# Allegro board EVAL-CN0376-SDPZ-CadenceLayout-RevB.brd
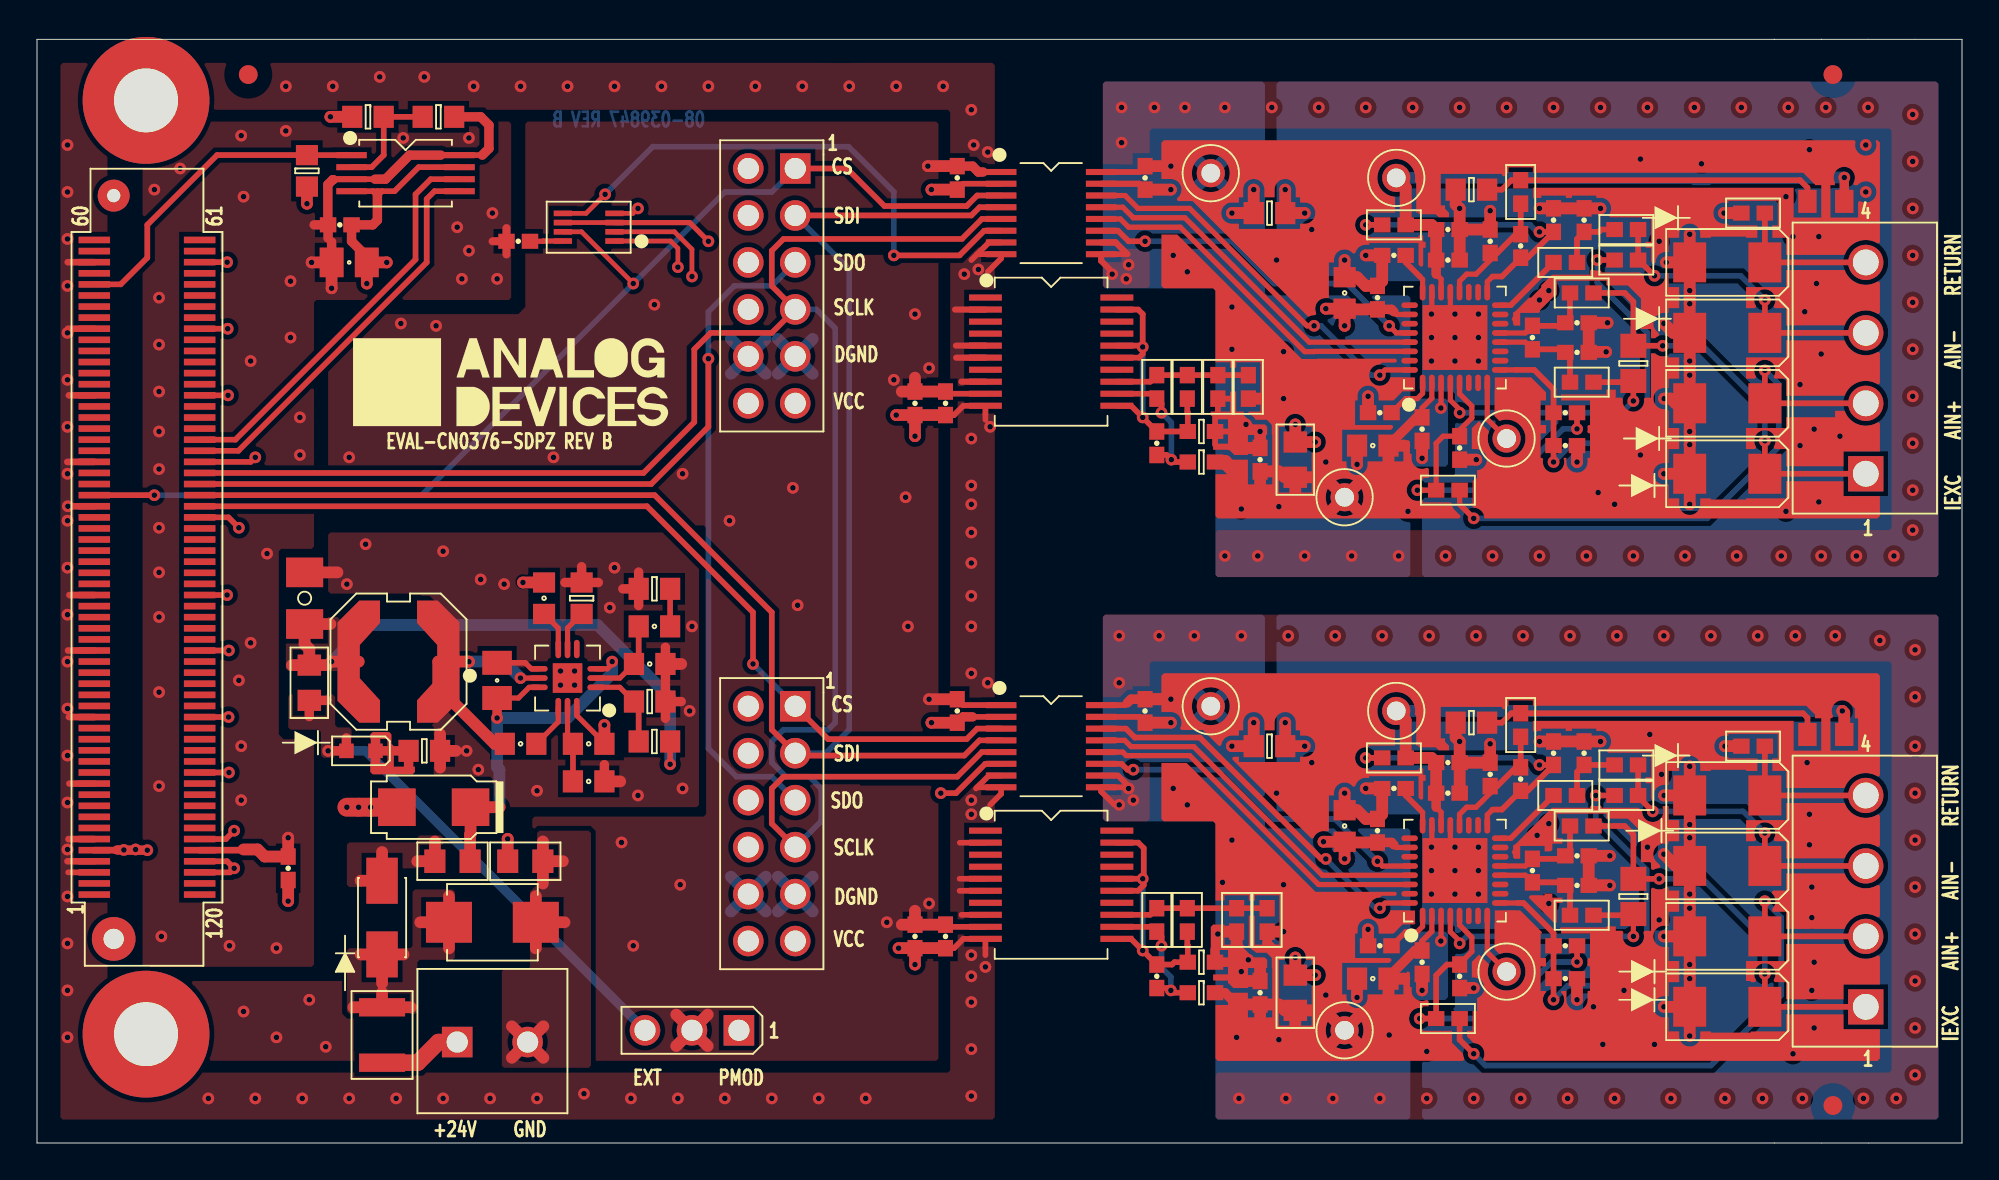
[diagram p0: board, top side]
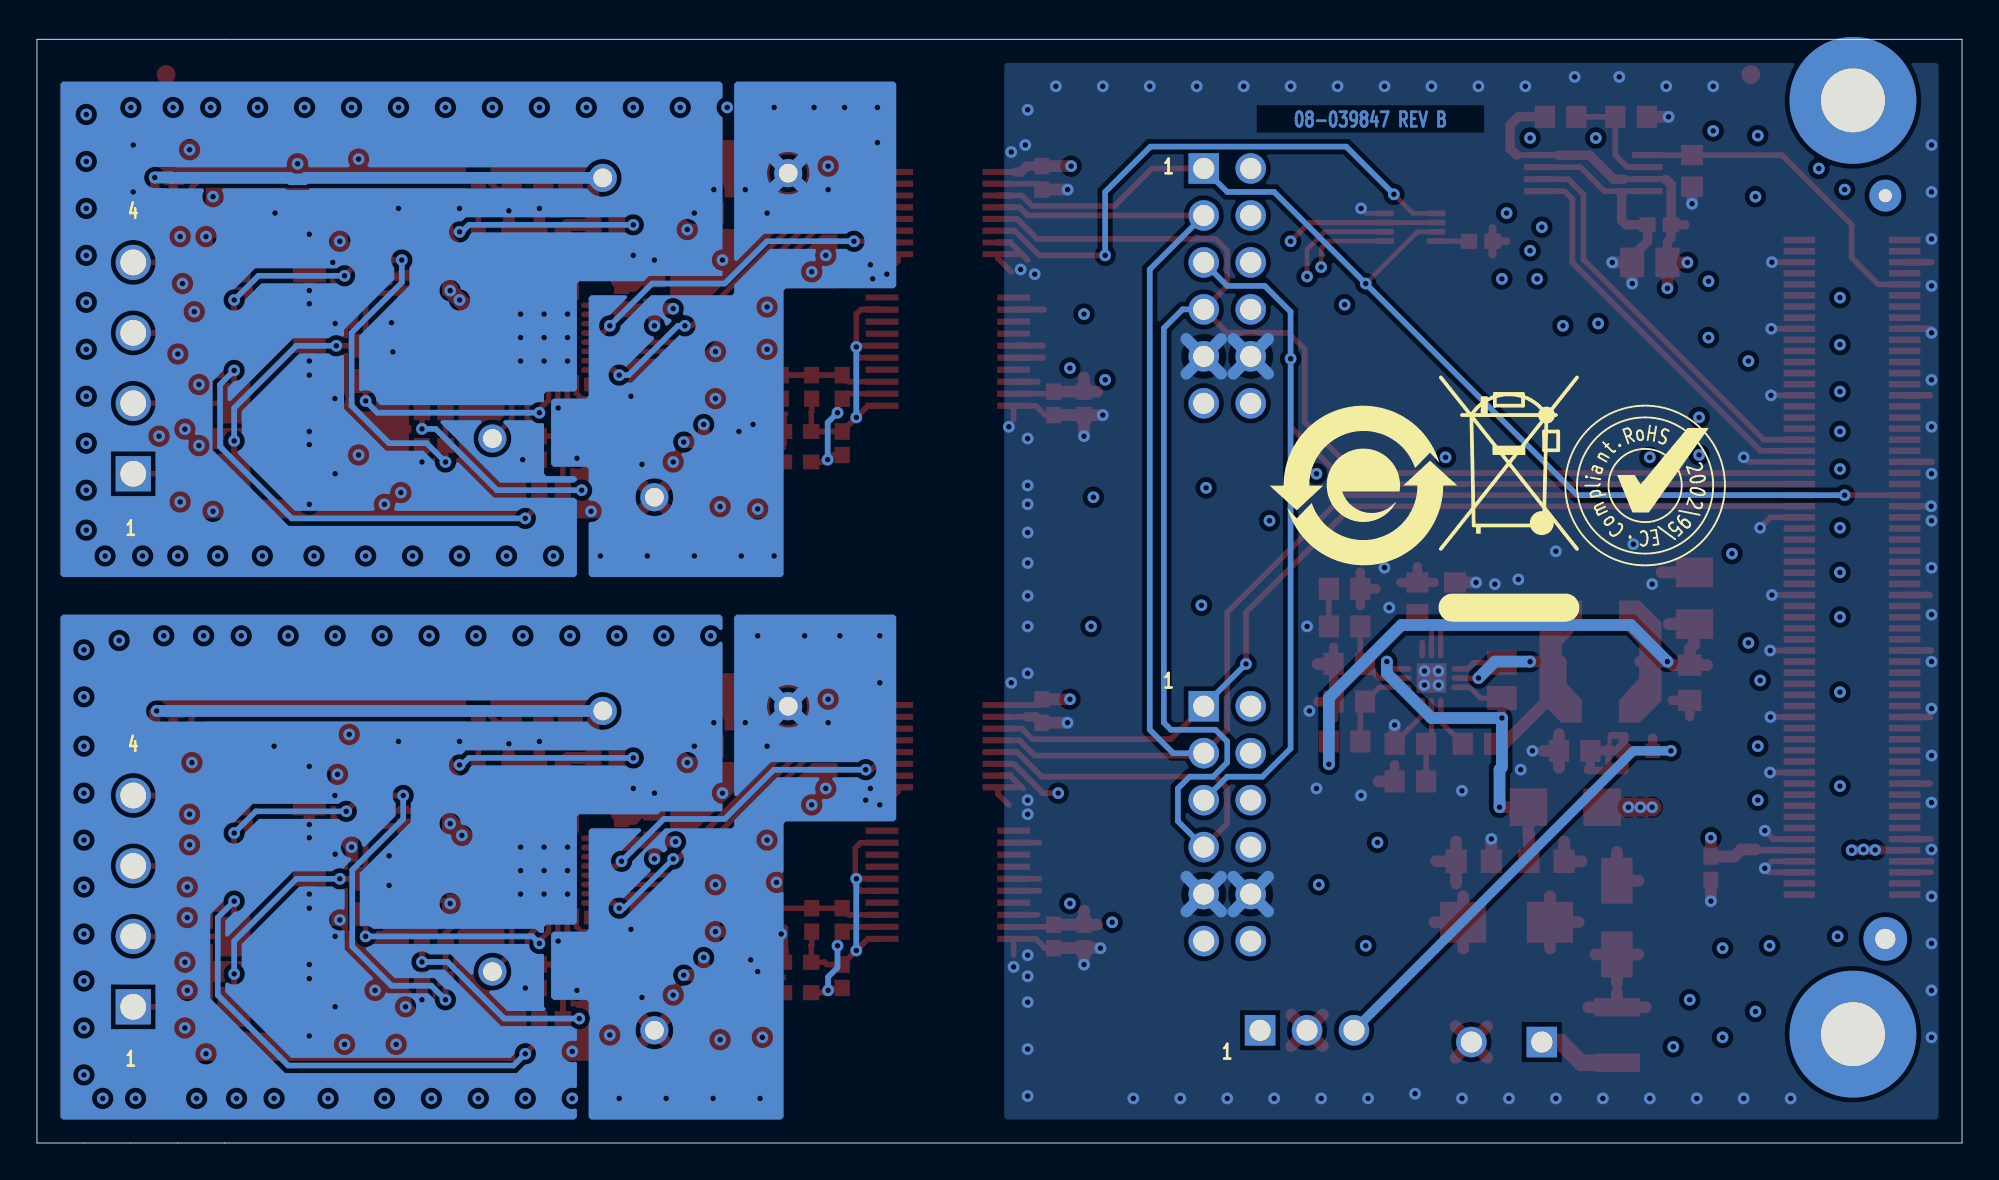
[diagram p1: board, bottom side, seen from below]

Outline 104.14 x 59.69 mm; copper layers: TOP, L2_GND, L3_PWR, BOTTOM. Coordinates in mm from the lower left corner of the outline.
Outline path: 0,59.69 0,0 104.14,0 104.14,59.69 0,59.69

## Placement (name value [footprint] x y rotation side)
AIN2A  5002  [CNKEY5001TP]  79.5 9.27 0 top
AIN2B  5002  [CNKEY5001TP]  79.5 38.1 0 top
C1  1000pF  [C0402]  76.96 9.02 270 top
C2  1000pF  [C0402]  82.68 8.89 180 top
C3  10000pF  [C0402]  82.68 10.67 180 top
C4  1000pF  [C0402]  83.31 13.93 0 top
C5  1000pF  [C0402]  83.31 15.53 180 top
C6  10000pF  [C0402]  80.9 14.73 90 top
C7  10000pF  [C0402]  80.26 19.68 270 top
C8  1000pF  [C0402]  78.61 19.94 90 top
C9  1UF  [C0603]  72.26 8.89 0 top
C10  0.1uF  [C0402]  74.93 9.78 90 top
C11  0.1uF  [C0402]  72.52 16.89 270 top
C12  1UF  [C0603]  70.74 17.14 270 top
C13  10uF  [C0402]  66.17 8.13 90 top
C14  0.1uF  [C0402]  72.64 10.67 0 top
C15  0.1uF  [C0402]  73.41 19.18 0 top
C16  0.1UF  [C0402]  60.58 9.02 90 top
C17  0.1UF  [C0402]  59.94 23.37 270 top
C18  0.1UF  [C0402]  49.15 11.17 270 top
C19  0.1UF  [C0402]  49.78 23.37 270 top
C20  10uF  [C0402]  47.5 11.17 270 top
C21  1000pF  [C0402]  76.96 37.59 270 top
C22  1000pF  [C0402]  82.68 37.72 180 top
C23  10000pF  [C0402]  82.68 39.5 180 top
C24  1000pF  [C0402]  83.31 42.76 0 top
C25  1000pF  [C0402]  83.31 44.36 180 top
C26  10000pF  [C0402]  80.9 43.56 90 top
C27  10000pF  [C0402]  80.26 48.51 270 top
C28  1000pF  [C0402]  78.61 48.77 90 top
C29  10uF  [C0402]  66.17 36.96 90 top
C30  0.1UF  [C0402]  60.58 37.85 90 top
C31  0.1UF  [C0402]  49.15 40 270 top
C32  10uF  [C0402]  47.5 40 270 top
C33  1UF  [C0603]  72.26 37.72 0 top
C34  0.1uF  [C0402]  74.93 38.61 90 top
C35  0.1uF  [C0402]  72.52 45.72 270 top
C36  1UF  [C0603]  70.74 45.97 270 top
C37  0.1uF  [C0402]  72.64 39.5 0 top
C38  0.1uF  [C0402]  73.41 48.01 0 top
C39  0.1UF  [C0402]  59.94 52.2 270 top
C40  0.1UF  [C0402]  49.78 52.2 270 top
C41  2.2uF  [C0805H60]  24.89 25.02 90 top
C42  1000pF  [C0603]  33.4 27.94 0 top
C43  8.2PF  [C0603]  33.15 25.91 0 top
C44  0.01uF  [C0603]  27.43 29.46 90 top
C45  0.01uF  [C0603]  26.16 21.59 180 top
C46  1uF  [C0603]  29.84 21.59 180 top
C47  1uF  [C0603]  29.84 19.56 0 top
C48  10uF  [C1206H71]  14.48 29.46 90 top
C49  0.1uF  [C0402]  13.59 14.86 90 top
C50  10uF  [C0805]  16.89 47.62 180 top
C51  0.1UF  [C0402]  16.38 49.66 180 top
C52  0.1uF  [C0402]  76.33 18.92 180 top
C53  0.1uF  [C0402]  76.33 47.75 180 top
C56  0.1uF  [C0402]  83.69 21.08 270 top
C57  1uF  [C0402]  76.33 20.57 0 top
C60  0.1uF  [C0402]  83.69 49.91 270 top
C61  1uF  [C0402]  76.33 49.4 0 top
C62  1000pF  [C0402]  82.04 21.08 90 top
C63  1000pF  [C0402]  82.04 49.91 90 top
C64  0.1UF  [C0402]  26.04 48.77 180 top
D1  SMBJ36CA  [DO214AA-5]  24.64 11.94 180 top
D2  SBR1A40SA-13  [SMA-2]  18.67 12.19 270 top
D3  SMAJ36A  [DO214AC]  91.44 7.37 180 top
D4  SMAJ36A  [DO214AC]  91.44 11.18 180 top
D5  SMAJ36A  [DO214AC]  91.44 14.99 180 top
D6  SMAJ36A  [DO214AC]  91.44 18.8 180 top
D7  SMAJ36A  [DO214AC]  91.44 36.19 180 top
D8  SMAJ36A  [DO214AC]  91.44 40 180 top
D9  SMAJ36A  [DO214AC]  91.44 43.81 180 top
D10  SMAJ36A  [DO214AC]  91.44 47.62 180 top
D11  MBRA340T3G  [SMA]  21.46 18.16 180 top
DS1  LNJ312G83RA (green)  [LED0603-2]  17.53 21.21 180 top
DVDD1  5002  [CNKEY5001TP]  70.74 6.1 0 top
DVDD2  5002  [CNKEY5001TP]  70.74 34.92 0 top
E1  0  [R0603]  66.67 21.46 180 top
E2  0  [R0603]  66.67 50.29 180 top
E3  330OHM  [L0805]  68.07 8.13 270 top
E4  330OHM  [L0805]  68.07 36.96 270 top
E5  330OHM  [L0805]  22.48 15.24 0 top
E6  330OHM  [L0805]  26.42 15.24 180 top
E7  1K OHM  [L0805]  14.73 24.89 270 top
E8  1KOHM AT 100MHZ  [L0603]  62.99 8.13 180 top
E9  1KOHM AT 100MHZ  [L0603]  62.99 9.78 180 top
E10  1KOHM AT 100MHZ  [L0603]  62.99 36.83 180 top
E11  1KOHM AT 100MHZ  [L0603]  62.99 38.48 180 top
F1  0.20A  [F1210]  18.67 5.84 90 top
GND1  5001  [CNKEY5001TP]  63.5 23.62 0 top
GND2  5001  [CNKEY5001TP]  63.5 52.45 0 top
L1  22uH  [LSMSQ236H138]  19.56 26.03 180 top
NOREF  -  []  25.65 41.15 0 top
NOREF#2  -  []  96.8 0 90 top
NOREF#3  -  [unnamed#2]  97.16 57.78 0 top
NOREF#4  -  [unnamed#2]  97.16 2.03 0 top
NOREF#5  -  []  0 0 0 top
NOREF#6  -  []  11.43 57.78 0 top
NOREF#7  -  [unnamed#2]  11.43 57.78 0 top
NOREF#8  -  []  -175.26 -209.3 0 top
NOREF#9  -  []  0 59.69 0 top
NOREF#10  -  []  182.25 258.06 0 top
NOREF#11  -  []  46.35 92.07 0 top
NOREF#12  -  []  101.6 59.69 0 top
NOREF#13  -  []  0 1.85 0 top
NOREF#14  -  []  97.79 -22.86 90 top
NOREF#15  -  []  0 -22.86 0 top
NOREF#16  -  []  -184.15 -219.71 0 top
NOREF#17  -  []  -182.88 -218.44 0 top
NOREF#18  -  []  0 59.69 0 top
NOREF#19  -  []  97.79 59.69 180 top
NOREF#20  -  []  101.6 59.69 0 top
NOREF#21  -  []  11.43 57.78 0 top
NOREF#22  -  []  -37.08 259.21 0 top
NOREF#23  -  []  0 59.69 270 top
NOREF#24  -  []  0 0 0 top
NOREF#25  -  []  186.82 5.84 180 bottom
NOREF#26  -  []  15.24 45.08 180 bottom
NOREF#27  -  []  32.38 35.56 180 bottom
NOREF#28  -  []  17.14 35.56 180 bottom
P1  1727036  [CNPHOENIX1727036]  98.93 7.37 90 top
P2  1727036  [CNPHOENIX1727036]  98.93 36.19 90 top
P3  1727010  [CNTH1X2H335_A]  22.73 5.46 0 top
P4  HTSW-106-08-G-D  [CNHDR2X6H330LD35_A]  41.02 23.62 270 top
P5  HTSW-106-08-G-D  [CNHDR2X6H330LD35_A]  41.02 52.7 270 top
PWR_SEL  SAMTECTSW10608GS3PIN  [CNBERG1X3H205LD36]  37.97 6.1 180 top
R1  3K  [R0402]  92.84 21.46 180 top
R3  3K  [R0402]  76.33 6.73 180 top
R4  3K  [R0402]  85.98 18.8 180 top
R5  3K  [R0402]  85.98 20.45 180 top
R6  3.92K  [R0805]  86.36 13.33 90 top
R8  3K  [R0402]  83.57 12.32 180 top
R9  3K  [R0402]  83.57 17.14 180 top
R10  5.62K  [R0603]  77.6 22.73 180 top
R11  3K  [R0402]  80.26 22.61 270 top
R12  10K  [R0402]  64.9 12.06 270 top
R13  16.9K  [R0402]  66.55 12.06 270 top
R14  10K  [R0402]  62.23 12.06 270 top
R15  16.9K  [R0402]  60.58 12.06 270 top
R16  3K  [R0402]  92.84 50.29 180 top
R18  3K  [R0402]  85.98 47.75 180 top
R19  3K  [R0402]  85.98 49.4 180 top
R20  3K  [R0402]  76.33 35.31 180 top
R21  3.92K  [R0805]  86.36 42.16 90 top
R23  3K  [R0402]  83.57 41.15 180 top
R24  3K  [R0402]  83.57 45.97 180 top
R25  5.62K  [R0603]  77.6 51.56 180 top
R26  3K  [R0402]  80.26 51.43 270 top
R27  10K  [R0402]  63.88 40.89 270 top
R28  16.9K  [R0402]  65.53 40.89 270 top
R29  10K  [R0402]  62.23 40.89 270 top
R30  16.9K  [R0402]  60.58 40.89 270 top
R31  294K  [R0603]  29.46 29.46 90 top
R32  32.4K  [R0603]  33.4 29.97 180 top
R33  13.7K  [R0603]  33.15 23.88 180 top
R34  61.9K  [R0603]  33.4 21.72 0 top
R35  130  [R0603]  20.95 21.21 0 top
R36  100K  [R0603]  14.61 52.58 270 top
R37  100K  [R0603]  21.72 55.5 180 top
R38  100K  [R0603]  17.91 55.5 180 top
R39  3K  [R0402]  73.41 20.83 180 top
R40  3K  [R0402]  73.41 49.66 180 top
R43  10  [R0402]  82.68 18.8 180 top
R46  10  [R0402]  82.68 47.62 180 top
REF1  5002  [CNKEY5001TP]  73.53 23.37 0 top
REF2  5002  [CNKEY5001TP]  73.53 52.2 0 top
RT1  10K  [R0805H51]  96.77 22.1 180 top
RT2  10K  [R0805H51]  96.77 50.93 180 top
SDP  FX8-120S-SV(21)  [CNHRSFX8-120S-SV_A]  5.95 31.14 90 top
U1  AD7124-4BCPZ  [QFN32_5X5_PAD3_5X3_5]  76.71 14.73 0 top
U2  ADUM5010ARSZ  [SSOP20-4]  54.86 13.97 270 top
U3  ADuM1441ARQZ  [QSOP16]  54.86 21.46 270 top
U4  ADUM5010ARSZ  [SSOP20-4]  54.86 42.8 270 top
U5  AD7124-4BCPZ  [QFN32_5X5_PAD3_5X3_5]  76.71 43.56 0 top
U6  ADuM1441ARQZ  [QSOP16]  54.86 50.29 270 top
U7  ADP2441ACPZ  [QFN12_3X3_PAD1_6X1_6]  28.7 25.15 90 top
U8  24LC32A-I/ST  [TSSOP8]  19.94 52.45 270 top
U9  SN74LVC2G125DCUT  [US8-2]  29.84 49.53 90 top

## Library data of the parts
AIN2A AIN2B DVDD1 DVDD2 REF1 REF2 = CNTP1P: User Part Number: UPN; alternate symbols: (CNBANANA_ALT); part number: CNTP1P_TH-5002,E006153,CNKEY5001TP
C1 C2 C4 C5 C8 C21 C22 C24 C25 C28 C62 C63 = CAP: Tolerance: 10; User Part Number: UPN; part number: CAP_SM-1000PF,50V,10,E020689,C0402; tolerance: 10
C3 C6 C23 C26 = CAP: Tolerance: 2; User Part Number: UPN; part number: CAP_SM-10000PF,16V,2,E015834,C0402; tolerance: 2
C7 C27 = CAP: Tolerance: 10; User Part Number: UPN; part number: CAP_SM-10000PF,50V,10,E021852,C0402; tolerance: 10
C9 C12 C33 C36 = CAP: Tolerance: 10; User Part Number: UPN; part number: CAP_SM-1UF,25V,10,E006992,C0603; tolerance: 10
C10 C11 C14 C15 C34 C35 C37 C38 C49 C52 C53 C56 C60 = CAP: Tolerance: -0.25; User Part Number: UPN; part number: CAP_SM-0.1UF,25V,-0.25,E011876,C0402; tolerance: -0.25
C13 C20 C29 C32 = CAP: Tolerance: 20; User Part Number: UPN; part number: CAP_SM-10UF,10V,20,E020928,C0402; tolerance: 20
C16-C19 C30 C31 C39 C40 C51 C64 = CAP: Tolerance: 10; User Part Number: UPN; part number: CAP_SM-0.1UF,16V,10,E007200,C0402; tolerance: 10
C41 = CAP: Tolerance: 20; User Part Number: UPN; part number: CAP_SM-2.2UF,50V,20,E016010,C0805H60; tolerance: 20
C42 = CAP: Tolerance: 10; User Part Number: UPN; part number: CAP_SM-1000PF,50V,10,E018586,C0603; tolerance: 10
C43 = CAP: Tolerance: 0.25PF; User Part Number: UPN; part number: CAP_SM-8.2PF,50V,0.25PF,E000346,C0603; tolerance: 0.25PF
C44 C45 = CAP: Tolerance: 5; User Part Number: UPN; part number: CAP_SM-0.01UF,25V,5,E012400,C0603; tolerance: 5
C46 C47 = CAP: Tolerance: 10; User Part Number: UPN; part number: CAP_SM-1UF,10V,10,E011783,C0603; tolerance: 10
C48 = CAP: Tolerance: 10; User Part Number: UPN; part number: CAP_SM-10UF,50V,10,E013961,C1206H71; tolerance: 10
C50 = CAP: Tolerance: 10; User Part Number: UPN; part number: CAP_SM-10UF,25V,10,E019080,C0805; tolerance: 10
C57 C61 = CAP: Tolerance: 20; User Part Number: UPN; part number: CAP_SM-1UF,16V,20,E020695,C0402; tolerance: 20
D1 = DIO_V3: Tolerance: N/A; User Part Number: UPN; part number: DIO_V3_SM-SMBJ36CA,36V,N/A,E019417,DO214AA-5; tolerance: N/A
D2 = DIO: User Part Number: UPN; Tolerance: N/A; alternate symbols: (DO15_ALT); part number: DIO_SM-SBR1A40SA-13,40V,N/A,E015547,SMA-2; tolerance: N/A
D3-D10 = DIO: User Part Number: UPN; Tolerance: 5; alternate symbols: (DO15_ALT); part number: DIO_SM-SMAJ36A,36V,5,E007236,DO214AC; tolerance: 5
D11 = DIOSCHOTTKY: User Part Number: UPN; Tolerance: N/A; alternate symbols: (SOD882L_ALT); part number: DIOSCHOTTKY_SM-MBRA340T3G,40V,N/A,E012714,SMA; tolerance: N/A
DS1 = DIOLED: Tolerance: N/A; User Part Number: UPN; part number: DIOLED_SM-LNJ312G83RA (GREEN),2.03V,N/A,E014696,LED0603-2; tolerance: N/A
E1 E2 = RES: Tolerance: 5; User Part Number: UPN; part number: RES_SM-0,E006826,1/10W,5,R0603; tolerance: 5
E3-E6 = FERRITE: Tolerance: 25; User Part Number: UPN; alternate symbols: (L1210H59_ALT); part number: FERRITE_SM-330OHM,25,E018120,L0805; tolerance: 25
E7 = FERRITE: Tolerance: N/A; User Part Number: UPN; alternate symbols: (L1210H59_ALT); part number: FERRITE_SM-1K OHM,N/A,E011583,L0805; tolerance: N/A
E8-E11 = FERRITE: Tolerance: 25; User Part Number: UPN; alternate symbols: (L1210H59_ALT); part number: FERRITE_SM-1KOHM AT 100MHZ ,25,E023240,L0603; tolerance: 25
F1 = FSFUSE: User Part Number: UPN; part number: FSFUSE_SM-0.20A,30V,E016947,F1210
GND1 GND2 = CNTP1P: User Part Number: UPN; alternate symbols: (CNBANANA_ALT); part number: CNTP1P_TH-5001,E005347,CNKEY5001TP
L1 = IND: User Part Number: UPN; Tolerance: 20; alternate symbols: (L0402-2,L0603_ALT,L1008L_ALT); part number: IND_SM-22UH,20,E022264,LSMSQ236H138; tolerance: 20
P1 P2 = CN4P: User Part Number: UPN; part number: CN4P_TH-1727036,E022262,CNPHOENIX1727036
P3 = CN2P: User Part Number: UPN; part number: CN2P_TH-1727010,E019958,CNTH1X2H335_A
P4 P5 = CN12P_V3: User Part Number: UPN; part number: CN12P_V3_TH-HTSW-106-08-G-D,E021590,CNHDR2X6H330LD35_A
PWR_SEL = CN3P: User Part Number: UPN; part number: CN3P_TH-SAMTECTSW10608GS3PIN,E000812,CNBERG1X3H205LD36
R1 R3-R5 R8 R9 R11 R16 R18-R20 R23 R24 R26 R39 R40 = RES: Tolerance: 1; User Part Number: UPN; part number: RES_SM-3K,E022429,1/10W,1,R0402; tolerance: 1
R6 R21 = RES: Tolerance: 0.1; User Part Number: UPN; part number: RES_SM-3.92K,E022280,1/10W,0.1,R0805; tolerance: 0.1
R10 R25 = RES: Tolerance: 0.1; User Part Number: UPN; part number: RES_SM-5.62K,E019549,1/16W,0.1,R0603; tolerance: 0.1
R12 R14 R27 R29 = RES: Tolerance: 1; User Part Number: UPN; part number: RES_SM-10K,E003751,1/16W,1,R0402; tolerance: 1
R13 R15 R28 R30 = RES: Tolerance: 1; User Part Number: UPN; part number: RES_SM-16.9K,E010876,1/16W,1,R0402; tolerance: 1
R31 = RES: Tolerance: 1; User Part Number: UPN; part number: RES_SM-294K,E021376,1/10W,1,R0603; tolerance: 1
R32 = RES: Tolerance: 1; User Part Number: UPN; part number: RES_SM-32.4K,E015281,1/16W,1,R0603; tolerance: 1
R33 = RES: Tolerance: 1; User Part Number: UPN; part number: RES_SM-13.7K,E022255,1/10W,1,R0603; tolerance: 1
R34 = RES: Tolerance: 1; User Part Number: UPN; part number: RES_SM-61.9K,E015338,1/10W,1,R0603; tolerance: 1
R35 = RES: Tolerance: 1; User Part Number: UPN; part number: RES_SM-130,E003676,1/10W,1,R0603; tolerance: 1
R36-R38 = RES: Tolerance: 1; User Part Number: UPN; part number: RES_SM-100K,E010279,1/10W,1,R0603; tolerance: 1
R43 R46 = RES: Tolerance: 1; User Part Number: UPN; part number: RES_SM-10,E003768,1/16W,1,R0402; tolerance: 1
RT1 RT2 = RESTHERM: Tolerance: 5; User Part Number: UPN; part number: RESTHERM_SM-10K,E018916,0.21W,5,R0805H51; tolerance: 5
SDP = CN120P_V4: User Part Number: UPN; part number: CN120P_V4_SM-FX8-120S-SV(21),E016993,CNHRSFX8-120S-SV_A
U1 U5 = AD7124_4: User Part Number: UPN; part number: AD7124_4_SM-AD7124-4BCPZ,E019053,QFN32_5X5_PAD3_5X3_5
U2 U4 = ADUM5010: User Part Number: UPN; part number: ADUM5010_SM-ADUM5010ARSZ,E014105,SSOP20-4
U3 U6 = ADUM144X_V2: User Part Number: UPN; part number: ADUM144X_V2_SM-ADUM1441ARQZ,E022333,QSOP16
U7 = ADP2441: User Part Number: UPN; part number: ADP2441_SM-ADP2441ACPZ,E017338,QFN12_3X3_PAD1_6X1_6
U8 = IC24FC256: User Part Number: UPN; part number: IC24FC256_SM-24LC32A-I/ST,E014553,TSSOP8
U9 = 74LVC2G125: User Part Number: UPN; part number: 74LVC2G125_SM-SN74LVC2G125DCUT,E014321,US8-2

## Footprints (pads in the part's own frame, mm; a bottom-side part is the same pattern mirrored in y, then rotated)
C0402
  rect 0.889x0.813 smd: 1(-0.635,0) 2(0.635,0)
C0603
  rect 1.092x1.194 smd: 1(-0.851,0) 2(0.851,0)
C0805
  rect 1.295x1.6 smd: 1(-0.953,0) 2(0.953,0)
C0805H60
  rect 1.295x1.6 smd: 1(-0.953,0) 2(0.953,0)
C1206H71
  rect 1.6x2.007 smd: 1(-1.397,0) 2(1.397,0)
CNBERG1X3H205LD36
  rect 1.651x1.651 hole 1.143: 1(0,0)
  round 1.651 hole 1.143: 2(2.54,0) 3(5.08,0)
CNHDR2X6H330LD35_A
  rect 1.651x1.651 hole 1.143: 1(0,0)
  round 1.651 hole 1.143: 2(2.54,0) 3(5.08,0) 4(7.62,0) 5(10.16,0) 6(12.7,0) 7(0,-2.54) 8(2.54,-2.54) 9(5.08,-2.54) 10(7.62,-2.54) 11(10.16,-2.54) 12(12.7,-2.54)
CNHRSFX8-120S-SV_A
  round 6.858 hole 3.454 unplated: (-25.25,0.051) (25.25,0.051)
  round 2.362 hole 1.092 unplated: (-20.099,1.801)
  round 1.727 hole 0.711 unplated: (20.099,1.801)
  rect 0.356x1.702 smd: 1(-17.701,2.85) 2(-17.099,2.85) 3(-16.5,2.85) 4(-15.9,2.85) 5(-15.301,2.85) 6(-14.699,2.85) 7(-14.1,2.85) 8(-13.5,2.85) 9(-12.901,2.85) 10(-12.301,2.85) 11(-11.699,2.85) 12(-11.1,2.85) 13(-10.5,2.85) 14(-9.901,2.85) 15(-9.299,2.85) 16(-8.7,2.85) 17(-8.1,2.85) 18(-7.501,2.85) 19(-6.901,2.85) 20(-6.299,2.85) 21(-5.7,2.85) 22(-5.1,2.85) 23(-4.501,2.85) 24(-3.899,2.85) 25(-3.299,2.85) 26(-2.7,2.85) 27(-2.101,2.85) 28(-1.501,2.85) 29(-0.899,2.85) 30(-0.3,2.85) 31(0.3,2.85) 32(0.899,2.85) 33(1.501,2.85) 34(2.101,2.85) 35(2.7,2.85) 36(3.299,2.85) 37(3.899,2.85) 38(4.501,2.85) 39(5.1,2.85) 40(5.7,2.85) 41(6.299,2.85) 42(6.901,2.85) 43(7.501,2.85) 44(8.1,2.85) 45(8.7,2.85) 46(9.299,2.85) 47(9.901,2.85) 48(10.5,2.85) 49(11.1,2.85) 50(11.699,2.85) 51(12.301,2.85) 52(12.901,2.85) 53(13.5,2.85) 54(14.1,2.85) 55(14.699,2.85) 56(15.301,2.85) 57(15.9,2.85) 58(16.5,2.85) 59(17.099,2.85) 60(17.701,2.85) 61(17.701,-2.85) 62(17.099,-2.85) 63(16.5,-2.85) 64(15.9,-2.85) 65(15.301,-2.85) 66(14.699,-2.85) 67(14.1,-2.85) 68(13.5,-2.85) 69(12.901,-2.85) 70(12.301,-2.85) 71(11.699,-2.85) 72(11.1,-2.85) 73(10.5,-2.85) 74(9.901,-2.85) 75(9.299,-2.85) 76(8.7,-2.85) 77(8.1,-2.85) 78(7.501,-2.85) 79(6.901,-2.85) 80(6.299,-2.85) 81(5.7,-2.85) 82(5.1,-2.85) 83(4.501,-2.85) 84(3.899,-2.85) 85(3.299,-2.85) 86(2.7,-2.85) 87(2.101,-2.85) 88(1.501,-2.85) 89(0.899,-2.85) 90(0.3,-2.85) 91(-0.3,-2.85) 92(-0.899,-2.85) 93(-1.501,-2.85) 94(-2.101,-2.85) 95(-2.7,-2.85) 96(-3.299,-2.85) 97(-3.899,-2.85) 98(-4.501,-2.85) 99(-5.1,-2.85) 100(-5.7,-2.85) 101(-6.299,-2.85) 102(-6.901,-2.85) 103(-7.501,-2.85) 104(-8.1,-2.85) 105(-8.7,-2.85) 106(-9.299,-2.85) 107(-9.901,-2.85) 108(-10.5,-2.85) 109(-11.1,-2.85) 110(-11.699,-2.85) 111(-12.301,-2.85) 112(-12.901,-2.85) 113(-13.5,-2.85) 114(-14.1,-2.85) 115(-14.699,-2.85) 116(-15.301,-2.85) 117(-15.9,-2.85) 118(-16.5,-2.85) 119(-17.099,-2.85) 120(-17.701,-2.85)
CNKEY5001TP
  round 1.524 hole 1.016: 1(0,0)
CNPHOENIX1727036
  rect 1.905x1.905 hole 1.397: 1(0,0)
  round 1.905 hole 1.397: 2(3.81,0) 3(7.62,0) 4(11.43,0)
CNTH1X2H335_A
  rect 1.651x1.651 hole 1.143: 1(0,0)
  round 1.651 hole 1.143: 2(3.81,0)
DO214AA-5
  rect 2.489x2.21 smd: 1(-2.349,0) 2(2.349,0)
DO214AC
  rect 1.778x2.159 smd: A(2.032,0) C(-2.032,0)
F1210
  rect 0.991x2.489 smd: 1(-1.499,0) 2(1.499,0)
L0603
  rect 0.889x0.813 smd: 1(-0.737,0) 2(0.737,0)
L0805
  rect 1.143x1.27 smd: 1(-0.953,0) 2(0.953,0)
LED0603-2
  rect 0.787x0.787 smd: A(0.787,0) C(-0.787,0)
LSMSQ236H138
  custom 0.575x0.575 smd: 1(-2.151,0) 2(2.151,0)
QFN12_3X3_PAD1_6X1_6
  oval 0.305x0.991 smd: 1(-0.5,-1.57) 2(0,-1.57) 3(0.5,-1.57) 7(0.5,1.57) 8(0,1.57) 9(-0.5,1.57)
  oval 0.991x0.305 smd: 4(1.57,-0.5) 5(1.57,0) 6(1.57,0.5) 10(-1.57,0.5) 11(-1.57,0) 12(-1.57,-0.5)
  rect 1.6x1.6 smd: PAD(0,0)
QFN32_5X5_PAD3_5X3_5
  oval 0.305x0.889 smd: 1(-1.75,-2.451) 2(-1.25,-2.451) 3(-0.749,-2.451) 4(-0.249,-2.451) 5(0.249,-2.451) 6(0.749,-2.451) 7(1.25,-2.451) 8(1.75,-2.451) 17(1.75,2.451) 18(1.25,2.451) 19(0.749,2.451) 20(0.249,2.451) 21(-0.249,2.451) 22(-0.749,2.451) 23(-1.25,2.451) 24(-1.75,2.451)
  oval 0.889x0.305 smd: 9(2.451,-1.75) 10(2.451,-1.25) 11(2.451,-0.749) 12(2.451,-0.249) 13(2.451,0.249) 14(2.451,0.749) 15(2.451,1.25) 16(2.451,1.75) 25(-2.451,1.75) 26(-2.451,1.25) 27(-2.451,0.749) 28(-2.451,0.249) 29(-2.451,-0.249) 30(-2.451,-0.749) 31(-2.451,-1.25) 32(-2.451,-1.75)
  rect 3.505x3.505 smd: PAD(0,0)
QSOP16
  rect 0.33x1.651 smd: 1(-2.223,-2.705) 2(-1.587,-2.705) 3(-0.953,-2.705) 4(-0.318,-2.705) 5(0.318,-2.705) 6(0.953,-2.705) 7(1.587,-2.705) 8(2.223,-2.705) 9(2.223,2.705) 10(1.587,2.705) 11(0.953,2.705) 12(0.318,2.705) 13(-0.318,2.705) 14(-0.953,2.705) 15(-1.587,2.705) 16(-2.223,2.705)
R0402
  rect 0.889x0.813 smd: 1(-0.635,0) 2(0.635,0)
R0603
  rect 1.092x1.194 smd: 1(-0.851,0) 2(0.851,0)
R0805
  rect 1.295x1.397 smd: 1(-0.953,0) 2(0.953,0)
R0805H51
  rect 0.991x1.245 smd: 1(-0.996,0) 2(0.996,0)
SMA
  rect 2.032x2.032 smd: A(1.994,0) C(-1.994,0)
SMA-2
  rect 2.489x1.702 smd: A(1.994,0) C(-1.994,0)
SSOP20-4
  rect 0.33x1.778 smd: 1(-2.926,-3.556) 2(-2.276,-3.556) 3(-1.626,-3.556) 4(-0.975,-3.556) 5(-0.325,-3.556) 6(0.325,-3.556) 7(0.975,-3.556) 8(1.626,-3.556) 9(2.276,-3.556) 10(2.926,-3.556) 11(2.926,3.556) 12(2.276,3.556) 13(1.626,3.556) 14(0.975,3.556) 15(0.325,3.556) 16(-0.325,3.556) 17(-0.975,3.556) 18(-1.626,3.556) 19(-2.276,3.556) 20(-2.926,3.556)
TSSOP8
  rect 0.33x1.651 smd: 1(-0.975,-2.921) 2(-0.325,-2.921) 3(0.325,-2.921) 4(0.975,-2.921) 5(0.975,2.921) 6(0.325,2.921) 7(-0.325,2.921) 8(-0.975,2.921)
unnamed#2
  round 1.016 smd: (0,0)
US8-2
  rect 0.305x0.991 smd: 1(-0.749,-1.394) 2(-0.249,-1.394) 3(0.249,-1.394) 4(0.749,-1.394) 5(0.749,1.394) 6(0.249,1.394) 7(-0.249,1.394) 8(-0.749,1.394)

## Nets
+3.3V: C18.1(N1) C19.1(N1) C20.1(N1) C31.1(N1) C32.1(N1) C40.1(N1) PWR_SEL.2(N2) U2.9(VDDP) U3.1(VDD1) U4.9(VDDP) U6.1(VDD1)
+3.3VIO: C49.2(N2) C50.2(N2) C51.2(N2) C64.2(N2) R37.1(N1) SDP.116(VIO(+3.3V)) U8.3(A2) U8.8(VCC)
+24V: C41.1(N1) D11.C(N) E5.2(N2) U7.3(EN) U7.9(VIN)
AGND1: C1.2(N2) C2.1(N1) C4.2(N2) C5.1(N1) C8.2(N2) C11.1(N1) C12.1(N1) C15.1(N1) C52.1(N1) C56.1(N1) C57.2(N2) C62.2(N2) D3.A(P) D4.A(P) D5.A(P) D6.A(P) E1.1(N1) R1.2(N2) R10.2(N2) U1.21(AIN7/IOUT/VBIAS/REFIN2(-)) U1.23(AVSS) U1.PAD
AGND2: C21.2(N2) C22.1(N1) C24.2(N2) C25.1(N1) C28.2(N2) C35.1(N1) C36.1(N1) C38.1(N1) C53.1(N1) C60.1(N1) C61.2(N2) C63.2(N2) D7.A(P) D8.A(P) D9.A(P) D10.A(P) E2.1(N1) R16.2(N2) R25.2(N2) U5.21(AIN7/IOUT/VBIAS/REFIN2(-)) U5.23(AVSS) U5.PAD
AGND_A: C18.2(N2) C19.2(N2) C20.2(N2) C31.2(N2) C32.2(N2) C40.2(N2) C41.2(N2) C43.2(N2) C44.2(N2) C46.1(N1) C47.2(N2) C48.2(N2) C49.1(N1) C50.1(N1) C51.1(N1) E6.2(N2) P4.5(GND1) P4.11(GND2) P5.5(GND1) P5.11(GND2) R31.2(N2) R32.2(N2) R33.1(N1) R35.2(N2) R36.2(N2) R38.2(N2) SDP.3(GND1) SDP.4(GND2) SDP.6(GND3) SDP.11(GND4) SDP.17(GND5) SDP.23(GND6) SDP.28(GND7) SDP.36(GND8) SDP.40(GND9) SDP.46(GND10) SDP.52(GND11) SDP.58(GND12) SDP.63(GND13) SDP.69(GND14) SDP.75(GND15) SDP.81(GND16) SDP.86(GND17) SDP.93(GND18) SDP.98(GND19) SDP.104(GND20) SDP.109(GND21) SDP.115(GND22) SDP.117(GND23) SDP.118(GND24) U2.2(GND1_1) U2.5(NC04) U2.6(NC05) U2.8(PWREN) U2.10(GND1_2) U3.2(GND1_1) U3.7(EN1) U3.8(GND1_2) U4.2(GND1_1) U4.5(NC04) U4.6(NC05) U4.8(PWREN) U4.10(GND1_2) U6.2(GND1_1) U6.7(EN1) U6.8(GND1_2) U7.7(PGND) U7.12(AGND) U7.PAD U8.4(VSS) U8.7(WP) U9.4(GND)
AGND_B: C29.2(N2) C33.1(N1) C34.1(N1) C37.1(N1) C39.2(N2) E2.2(N2) E11.1(N1) GND2.1(N1) R27.2(N2) U5.3(DGND) U6.9(GND2_1) U6.10(EN2) U6.15(GND2_2)
AVDD1: C11.2(N2) C12.2(N2) E3.1(N1) U1.26(AVDD)
AVDD2: C35.2(N2) C36.2(N2) E4.1(N1) U5.26(AVDD)
DVDD1: C9.2(N2) C10.2(N2) C13.1(N1) C17.1(N1) DVDD1.1(N1) E3.2(N2) E8.1(N1) R13.2(N2) U1.2(IOVDD) U3.16(VDD2)
DVDD2: C29.1(N1) C33.2(N2) C34.2(N2) C39.1(N1) DVDD2.1(N1) E4.2(N2) E10.1(N1) R28.2(N2) U5.2(IOVDD) U6.16(VDD2)
GND_ISO: C9.1(N1) C10.1(N1) C13.2(N2) C14.1(N1) C17.2(N2) E1.2(N2) E9.1(N1) GND1.1(N1) R12.2(N2) U1.3(DGND) U3.9(GND2_1) U3.10(EN2) U3.15(GND2_2)
VCC_PMOD: P4.6(VCC1) P4.12(VCC2) P5.6(VCC1) P5.12(VCC2) PWR_SEL.1(N1)
CS_A_SDP: P4.1(P1) SDP.85(SPI_SEL_A) U3.3(VIA) U9.1(1OE_N)
CS_B_SDP: P5.1(P1) SDP.37(SPI_SEL_B_N) U6.3(VIA) U9.7(2OE_N)
CS_ISO1: U1.32(CS_N) U3.14(VOA)
CS_ISO2: U5.32(CS_N) U6.14(VOA)
IEXC_A: R6.1(N1) R8.1(N1) U1.4(AIN0/IOUT/VBIAS)
IEXC_B: R21.1(N1) R23.1(N1) U5.4(AIN0/IOUT/VBIAS)
SCL_0: SDP.79(SCL_0) U8.6(SCL)
SCLK_ISO1: U1.30(SCLK) U3.12(VOC)
SCLK_ISO2: U5.30(SCLK) U6.12(VOC)
SCLK_SDP: P4.4(P4) P5.4(P4) SDP.82(SPI_CLK) U3.5(VIC) U6.5(VIC)
SDA_0: SDP.80(SDA_0) U8.5(SDA)
SDI_ISO1: U1.29(DIN) U3.13(VOB)
SDI_ISO2: U5.29(DIN) U6.13(VOB)
SDI_SDP: P4.2(P2) P5.2(P2) SDP.84(SPI_MOSI) U3.4(VIB) U6.4(VIB)
SDO_A_SDP: U3.6(VOD) U9.2(1A)
SDO_B_SDP: U6.6(VOD) U9.5(2A)
SDO_SDP: P4.3(P3) P5.3(P3) SDP.83(SPI_MISO) U9.3(2Y) U9.6(1Y)
UNNAMED_2_AD71244_I1_AIN1: C1.1(N1) C3.1(N1) R3.2(N2) U1.5(AIN1/IOUT/VBIAS)
UNNAMED_2_AD71244_I1_AIN2: AIN2A.1(N1) U1.8(AIN2/IOUT/VBIAS/P1)
UNNAMED_2_AD71244_I1_AIN3: C2.2(N2) C3.2(N2) R4.2(N2) U1.9(AIN3/IOUT/VBIAS/P2)
UNNAMED_2_AD71244_I1_AIN4: R43.2(N2) U1.16(AIN4/IOUT/VBIAS)
UNNAMED_2_AD71244_I1_AIN5: C7.2(N2) C62.1(N1) R39.2(N2) U1.17(AIN5/IOUT/VBIAS)
UNNAMED_2_AD71244_I1_AIN6: C7.1(N1) C8.1(N1) R11.2(N2) U1.20(AIN6/IOUT/VBIAS/REFIN2(+))
UNNAMED_2_AD71244_I1_DOUT: U1.28(DOUT/RDY_N) U3.11(VID)
UNNAMED_2_AD71244_I1_REFIN1: C5.2(N2) C6.2(N2) R9.2(N2) U1.13(REFIN1(-))
UNNAMED_2_AD71244_I1_REFIN1_1: C4.1(N1) C6.1(N1) R8.2(N2) U1.12(REFIN1(+))
UNNAMED_2_AD71244_I1_REGCAPA: C15.2(N2) U1.24(REGCAPA)
UNNAMED_2_AD71244_I1_REGCAPD: C14.2(N2) U1.1(REGCAPD)
UNNAMED_2_ADUM5010_I94_GNDISO1: C16.2(N2) E9.2(N2) R14.2(N2) U2.11(GNDISO1) U2.15(NC08) U2.16(NC09) U2.19(GNDISO2)
UNNAMED_2_ADUM5010_I94_VSEL: R12.1(N1) R13.1(N1) R14.1(N1) R15.1(N1) U2.13(VSEL)
UNNAMED_2_CAP_I52_N1: C16.1(N1) E8.2(N2) R15.2(N2) U2.12(VISO)
UNNAMED_2_CAP_I124_N2: C56.2(N2) R5.2(N2) R43.1(N1)
UNNAMED_2_CN4P_I6_N2: D4.C(N) P1.2(N2) R3.1(N1)
UNNAMED_2_CN4P_I6_N3: D5.C(N) P1.3(N3) R4.1(N1) R5.1(N1)
UNNAMED_2_CN4P_I6_N4: D6.C(N) P1.4(N4) R1.1(N1)
UNNAMED_2_RES_I79_N1: D3.C(N) P1.1(N1) R6.2(N2) R9.1(N1)
UNNAMED_2_RES_I105_N1: R10.1(N1) R11.1(N1) RT1.2(N2)
UNNAMED_3_AD71244_I22_AIN1: C21.1(N1) C23.1(N1) R20.2(N2) U5.5(AIN1/IOUT/VBIAS)
UNNAMED_3_AD71244_I22_AIN2: AIN2B.1(N1) U5.8(AIN2/IOUT/VBIAS/P1)
UNNAMED_3_AD71244_I22_AIN3: C22.2(N2) C23.2(N2) R18.2(N2) U5.9(AIN3/IOUT/VBIAS/P2)
UNNAMED_3_AD71244_I22_AIN4: R46.2(N2) U5.16(AIN4/IOUT/VBIAS)
UNNAMED_3_AD71244_I22_AIN5: C27.2(N2) C63.1(N1) R40.2(N2) U5.17(AIN5/IOUT/VBIAS)
UNNAMED_3_AD71244_I22_AIN6: C27.1(N1) C28.1(N1) R26.2(N2) U5.20(AIN6/IOUT/VBIAS/REFIN2(+))
UNNAMED_3_AD71244_I22_DOUT: U5.28(DOUT/RDY_N) U6.11(VID)
UNNAMED_3_AD71244_I22_REFIN1: C25.2(N2) C26.2(N2) R24.2(N2) U5.13(REFIN1(-))
UNNAMED_3_AD71244_I22_REFIN1_1: C24.1(N1) C26.1(N1) R23.2(N2) U5.12(REFIN1(+))
UNNAMED_3_AD71244_I22_REGCAPA: C38.2(N2) U5.24(REGCAPA)
UNNAMED_3_AD71244_I22_REGCAPD: C37.2(N2) U5.1(REGCAPD)
UNNAMED_3_ADUM5010_I79_GNDISO1: C30.2(N2) E11.2(N2) R29.2(N2) U4.11(GNDISO1) U4.15(NC08) U4.16(NC09) U4.19(GNDISO2)
UNNAMED_3_ADUM5010_I79_VISO: C30.1(N1) E10.2(N2) R30.2(N2) U4.12(VISO)
UNNAMED_3_ADUM5010_I79_VSEL: R27.1(N1) R28.1(N1) R29.1(N1) R30.1(N1) U4.13(VSEL)
UNNAMED_3_CAP_I95_N2: C60.2(N2) R19.2(N2) R46.1(N1)
UNNAMED_3_CN4P_I61_N1: D7.C(N) P2.1(N1) R21.2(N2) R24.1(N1)
UNNAMED_3_CN4P_I61_N2: D8.C(N) P2.2(N2) R20.1(N1)
UNNAMED_3_CN4P_I61_N3: D9.C(N) P2.3(N3) R18.1(N1) R19.1(N1)
UNNAMED_3_CN4P_I61_N4: D10.C(N) P2.4(N4) R16.1(N1)
UNNAMED_3_RES_I20_N1: R25.1(N1) R26.1(N1) RT2.2(N2)
UNNAMED_4_ADP2441_I109_BST: C45.1(N1) U7.10(BST)
UNNAMED_4_ADP2441_I109_COMP: C42.1(N1) C43.1(N1) U7.2(COMP)
UNNAMED_4_ADP2441_I109_FB: R33.2(N2) R34.1(N1) U7.1(FB)
UNNAMED_4_ADP2441_I109_FREQ: R31.1(N1) U7.5(FREQ)
UNNAMED_4_ADP2441_I109_SS: C44.1(N1) U7.6(SS/TRK)
UNNAMED_4_ADP2441_I109_SW: C45.2(N2) L1.1(N1) U7.8(SW)
UNNAMED_4_ADP2441_I109_VCC: C46.2(N2) C47.1(N1) U7.11(VCC)
UNNAMED_4_CAP_I209_N2: C42.2(N2) R32.1(N1)
UNNAMED_4_CAP_I219_N1: C48.1(N1) E7.1(N1) L1.2(N2) R34.2(N2)
UNNAMED_4_CN2P_I225_N1: F1.1(N1) P3.1(N1)
UNNAMED_4_CN2P_I225_N2: D1.1(N1) E6.1(N1) P3.2(N2)
UNNAMED_4_CN3P_I234_N3: DS1.A(P) E7.2(N2) PWR_SEL.3(N3)
UNNAMED_4_DIO_I227_N: D2.C(N) E5.1(N1)
UNNAMED_4_DIO_I227_P: D1.2(N2) D2.A(P) F1.2(N2)
UNNAMED_4_DIOLED_I134_N: DS1.C(N) R35.1(N1)
UNNAMED_5_74LVC2G125_I79_VCC: C64.1(N1) U9.8(VCC)
UNNAMED_5_CN120PV4_I1_EEPROMA0: R36.1(N1) SDP.56(EEPROM_A0) U8.1(A0)
UNNAMED_5_CN120PV4_I1_USBVBUS: D11.A(P) SDP.5(USB_VBUS)
UNNAMED_5_IC24FC256_I3_A1: R37.2(N2) R38.1(N1) U8.2(A1)
VREF1: C52.2(N2) C57.1(N1) R39.1(N1) REF1.1(N1) RT1.1(N1) U1.22(REFOUT)
VREF2: C53.2(N2) C61.1(N1) R40.1(N1) REF2.1(N1) RT2.1(N1) U5.22(REFOUT)

Pads without a net: P4 7 8 9 10; P5 7 8 9 10; SDP 1 2 7 8 9 10 12 13 14 15 16 18 19 20 21 22 24 25 26 27 29 30 31 32 33 34 35 38 39 41 42 43 44 45 47 48 49 50 51 53 54 55 57 59 60 61 62 64 65 66 67 68 70 71 72 73 74 76 77 78 87 88 89 90 91 92 94 95 96 97 99 100 101 102 103 105 106 107 108 110 111 112 113 114 119 120; U1 6 7 10 11 14 15 18 19 25 27 31; U2 1 3 4 7 14 17 18 20; U4 1 3 4 7 14 17 18 20; U5 6 7 10 11 14 15 18 19 25 27 31; U7 4

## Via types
v1: diameter 0.635, hole 0.305, TOP to BOTTOM, 511 vias

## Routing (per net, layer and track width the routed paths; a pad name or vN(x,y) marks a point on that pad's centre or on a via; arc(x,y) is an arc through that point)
+3.3V: length 28.9
  TOP w0.305: C31.1 49.27,40.52 U4.9 ; C19.1 50.1,23.68 U3.1 ; C18.1 49.27,11.69 U2.9 ; 51.18,52.51 U6.1
  TOP w0.508: 51.18,52.51 50.93,52.51 50.61,52.83 C40.1
  TOP w0.635: C20.1 46.78,11.81 ; C20.1 C18.1 ; C20.1 47.5,12.56 ; PWR_SEL.2 34.58,6.95 ; PWR_SEL.2 34.58,5.25 ; PWR_SEL.2 36.28,5.25 ; PWR_SEL.2 36.28,6.95 ; C19.1 v1(48.26,24) ; 46.78,40.64 C32.1 ; C32.1 47.5,41.39 ; C32.1 C31.1 ; C40.1 v1(48.2,52.83)
  L3_PWR w0.635: PWR_SEL.2 36.38,7.04 ; PWR_SEL.2 34.49,7.04 ; PWR_SEL.2 36.38,5.15 ; PWR_SEL.2 34.49,5.15
  vias: v1(11.18,7.11) v1(12.95,5.71) v1(14.73,7.75) v1(15.62,5.21) v1(16.89,37.08) v1(19.69,44.32) v1(21.59,44.2) v1(27.94,37.08) v1(31.62,16.26) v1(32.26,10.67) v1(33.4,45.34) v1(34.8,13.97) v1(34.92,36.19) v1(37.47,33.66) v1(40.89,35.43) v1(41.15,29.08) v1(45.97,11.94) v1(46.35,41.27) v1(46.99,34.92) v1(47.12,27.94) v1(47.5,44.83) v1(48.26,41.91) v1(48.26,12.95)
+3.3VIO: length 28.2
  TOP w0.305: 24.09,53.43 U8.8 21.84,53.43 ; 18.29,52.13 U8.3 16.06,52.13 16.03,52.1 ; 11.14,15.84 11.18,15.88
  TOP w0.356: SDP.116 11.14,15.84
  TOP w0.432: C64.2 24.65,48.77 ; C64.2 25.4,48.05 ; C64.2 25.4,49.48
  TOP w0.508: C51.2 15.74,49.67 15.74,51.83 16,52.1 16.03,52.1 ; C51.2 15.75,48.94 ; C51.2 15,49.66 ; C50.2 15.94,48.73 ; 21.84,53.43 20.15,53.43 18.85,52.13 18.29,52.13 ; R37.1 24,55.5 24.45,55.05 24.45,53.79 24.09,53.43
  TOP w0.635: v1(14.86,47.62) C50.2 v1(15.94,46.23) ; 11.18,15.88 11.94,15.88 12.32,15.49 C49.2 v1(13.59,16.51)
  vias: v1(6.35,51.56) v1(6.6,45.72) v1(6.6,43.18) v1(6.6,40.64) v1(6.6,38.48) v1(6.6,36.45) v1(6.6,33.27) v1(6.6,30.86) v1(6.6,28.45) v1(6.6,24.38) v1(6.6,19.3) v1(6.73,11.18) v1(7.75,52.7) v1(10.41,10.67) v1(10.92,25.02) v1(11.05,54.48) v1(11.05,21.46) v1(11.05,18.54) v1(11.18,51.18) v1(11.56,42.29) v1(11.56,27.05) v1(12.45,31.88) v1(12.95,10.54) v1(13.46,54.74) v1(13.72,46.61) v1(13.72,43.56) v1(14.22,39.24) v1(14.22,37.21) v1(19.81,54.36) v1(22.73,49.53) v1(22.99,46.74) v1(23.37,54.36) v1(23.37,48.26) v1(24.64,50.29) v1(24.89,46.74)
+24V: length 21.9
  TOP w0.279: U7.3 30.85,25.65 31.11,25.91 v1(31.11,26.03) ; C41.1 26.05,24.07 26.63,24.65 U7.9
  TOP w0.508: C41.1 v1(24.89,22.99)
  TOP w0.635: v1(25.02,18.16) D11.C 23.46,16.7 23.43,16.67 E5.2
  BOTTOM w0.635: v1(25.02,18.16) 25.02,20.19 24.89,20.32 v1(24.89,22.99) 28.7,22.99 31.11,25.4 v1(31.11,26.03)
AGND1: length 47.3
  TOP w0.279: v1(75.44,16) 75.46,16.02 U1.23 ; v1(76.71,16) 76.46,16.25 U1.21
  TOP w0.635: v1(70.74,18.92) C12.1 71.41,18 71.88,17.53 C11.1 72.77,17.78 C15.1 v1(71.88,19.18) ; C2.1 v1(83.31,7.75) ; v1(85.09,13.93) 83.95,13.93 83.95,15.53 v1(85.09,15.53) ; D5.A v1(89.41,13.46) v1(89.41,12.7) D4.A ; D5.A 88.65,14.99 v1(88.01,15.62) ; D5.A v1(89.41,16.51) v1(89.41,17.22) D6.A ; R1.2 v1(91.31,21.46) ; D3.A v1(89.41,8.89) v1(89.41,9.65) D4.A ; D3.A v1(88.01,7.37) ; D3.A v1(89.41,5.79) ; R10.2 76.75,21.93 v1(76.96,21.72) C57.2 ; D4.A v1(88.01,11.18) ; C1.2 v1(77.72,8.38) ; C57.2 C8.2 v1(78.61,21.59) ; C57.2 C52.1 ; D6.A v1(89.41,20.37) ; D6.A v1(88.02,18.8) ; v1(84.58,21.72) C56.1 C62.2 v1(81.28,21.72) ; v1(67.53,22.73) E1.1 v1(68.58,21.46)
  vias: v1(75.44,14.73) v1(75.44,13.46) v1(76.71,14.73) v1(76.71,13.46) v1(77.98,16) v1(77.98,14.73) v1(77.98,13.46)
AGND2: length 46.9
  TOP w0.279: v1(76.71,44.83) 76.46,45.08 U5.21 ; U5.23 75.46,44.85 v1(75.44,44.83)
  TOP w0.635: R25.2 76.75,50.76 v1(76.96,50.55) C61.2 ; v1(81.28,50.55) C63.2 C60.1 v1(84.58,50.55) ; D8.A v1(89.41,38.48) v1(89.41,37.77) D7.A ; D8.A 88.65,40 88.39,40.26 v1(88.02,40.26) ; D8.A v1(89.41,41.53) v1(89.41,42.29) D9.A ; C61.2 C28.2 v1(78.61,50.42) ; C61.2 C53.1 ; 83.95,42.79 83.95,42.76 ; 83.95,42.79 83.95,44.36 v1(84.96,44.36) ; 83.95,42.79 v1(84.89,42.79) ; D7.A v1(89.41,34.54) ; D7.A v1(88.01,36.19) ; v1(67.53,51.56) E2.1 v1(68.58,50.29) ; C22.1 v1(83.31,36.83) ; D9.A 88.52,43.81 v1(88.01,44.32) ; D9.A v1(89.41,45.39) v1(89.41,46.1) D10.A ; D10.A v1(88.14,47.62) ; D10.A v1(89.41,49.15) ; v1(77.86,36.96) C21.2 ; R16.2 v1(91.26,50.29) ; v1(70.74,47.75) C36.1 71.41,46.82 71.88,46.35 C35.1 72.77,46.61 C38.1 v1(71.88,48.01)
  vias: v1(75.44,43.56) v1(75.44,42.29) v1(76.71,43.56) v1(76.71,42.29) v1(77.98,44.83) v1(77.98,43.56) v1(77.98,42.29) v1(98.93,53.97) v1(98.93,51.43)
AGND_A: length 168
  TOP w0.254: U9.4 32.25,50.28 v1(32.51,50.55)
  TOP w0.279: U7.12 29.2,23.12 30.7,21.63 ; 26.42,25.97 26.74,25.65 U7.7
  TOP w0.305: SDP.75 v1(10.34,40.44) ; U2.2 49.92,16.24 ; U6.7 51.5,48.7 50.86,48.07 ; 18.41,51.22 18.67,51.48 ; 18.41,51.22 18.16,51.48 ; 18.41,51.22 18.41,51.48 ; 18.67,51.48 19.34,51.48 20.65,52.78 U8.7 ; 18.67,51.48 18.41,51.48 ; v1(11.81,37.08) 11.56,36.84 SDP.81 ; SDP.86 10.36,33.84 v1(10.92,33.27) ; SDP.115 10.22,16.44 v1(10.67,16.89) ; 18.16,51.48 U8.4 ; 18.16,51.48 18.41,51.48 ; SDP.98 v1(10.38,26.64) ; U3.2 50.61,23.05 ; SDP.109 v1(10.39,20.04) ; 50.8,19.17 50.86,19.24 ; 50.86,19.24 U3.8 52.16,18.88 51.56,18.29 ; 50.86,19.24 51.5,19.87 U3.7 ; 51.44,47.12 52.16,47.84 U6.8 50.86,48.07 ; 50.86,48.07 50.55,47.75 ; U2.6 49.91,13.64 ; C31.2 49.61,39.37 50.11,39.87 U4.10 51.31,39.12 ; SDP.118 10.45,14.64 v1(10.67,14.86) 10.29,15.24 SDP.117 ; 51.31,10.16 U2.10 50.11,11.04 49.61,10.54 C18.2 ; SDP.104 v1(10.36,23.04) ; U2.5 49.91,14.29 ; SDP.63 v1(10.29,47.64) ; U6.2 50.1,51.88 C40.2 ; SDP.3 1.68,14.64 ; U2.8 50.01,12.34 ; C41.2 26.42,25.97 ; SDP.93 v1(10.29,29.64) ; SDP.69 v1(10.32,44.04)
  TOP w0.33: U4.6 49.73,42.47 ; U4.2 49.67,45.07 ; U4.8 50.01,41.17 ; U4.5 49.71,43.12
  TOP w0.356: SDP.40 1.64,36.84 ; SDP.23 1.68,26.64 ; SDP.6 1.71,16.44 ; 1.76,19.44 SDP.11 ; SDP.17 1.73,23.04 ; 1.76,29.64 SDP.28 ; SDP.52 1.68,44.04 ; 1.66,47.64 SDP.58 ; SDP.4 1.65,15.24 ; SDP.36 v1(1.67,34.44) ; SDP.46 1.73,40.44
  TOP w0.508: R33.1 34,22.97 ; R33.1 34,24.78 ; R33.1 34.85,23.88 ; 34,26.81 C43.2 34,25 ; R31.2 29.46,31.17 ; R31.2 30.37,30.31 ; R31.2 28.56,30.31 ; R32.2 32.55,29.07 ; R32.2 31.7,29.97 ; R32.2 32.55,30.88 ; 50.61,23.05 50.1,23.05 C19.2 ; C47.2 30.7,20.46 ; 18.41,51.22 18.41,49.91 18.16,49.66 C51.1 17.02,48.77 17.84,47.94 C50.1
  TOP w0.635: v1(18.92,47.62) C50.1 v1(17.84,46.48) ; v1(48.39,51.56) C40.2 ; C19.2 v1(48.39,22.73) ; C43.2 34.85,25.91 ; E6.2 v1(25.46,16.45) ; C32.2 v1(47.5,38.23) ; C32.2 C31.2 ; C32.2 v1(46.48,39.37) ; R38.2 v1(15.88,55.5) ; C20.2 C18.2 ; C20.2 v1(47.5,9.65) ; C20.2 v1(46.61,10.54) ; C47.2 31.55,19.56 ; C48.2 16.26,30.86 ; C44.2 v1(26.29,30.31) ; C49.1 v1(13.59,13.08) ; R36.2 v1(14.61,50.8) ; R35.2 21.81,20.3 ; R35.2 22.66,21.21 ; R35.2 21.81,22.11 ; C46.1 v1(30.7,22.61)
  L2_GND w0.635: 41.02,13.46 41.96,12.52 ; 41.02,13.46 40.08,14.4 ; 41.02,13.46 40.08,12.52 ; 41.02,13.46 41.96,14.4 ; P5.5 41.96,41.6 ; P5.5 41.96,43.49 ; P5.5 40.08,43.49 ; P5.5 40.08,41.6 ; 38.48,13.46 39.42,14.4 ; 38.48,13.46 39.42,12.52 ; 38.48,13.46 37.54,14.4 ; 38.48,13.46 37.54,12.52 ; P5.11 39.42,41.6 ; P5.11 37.54,41.6 ; P5.11 37.54,43.49 ; P5.11 39.42,43.49
  BOTTOM w0.635: 40.08,12.52 41.02,13.46 ; 41.02,13.46 41.96,14.4 ; 41.02,13.46 41.96,12.52 ; 41.02,13.46 40.08,14.4 ; 37.54,14.4 38.48,13.46 ; 38.48,13.46 39.42,14.4 ; 38.48,13.46 39.42,12.52 ; 38.48,13.46 37.54,12.52 ; 40.08,41.6 P5.5 ; P5.5 41.96,43.49 ; P5.5 40.08,43.49 ; P5.5 41.96,41.6 ; 37.54,43.49 P5.11 ; P5.11 37.54,41.6 ; P5.11 39.42,41.6 ; P5.11 39.42,43.49
  vias: v1(1.65,53.97) v1(1.65,51.43) v1(1.65,48.89) v1(1.65,46.35) v1(1.65,43.81) v1(1.65,41.27) v1(1.65,38.73) v1(1.65,36.19) v1(1.65,33.66) v1(1.65,31.11) v1(1.65,28.57) v1(1.65,26.03) v1(1.65,23.49) v1(1.65,20.95) v1(1.65,18.41) v1(1.65,15.88) v1(1.65,13.33) v1(1.65,10.79) v1(1.65,8.25) v1(1.65,5.71) v1(9.27,2.41) v1(11.81,2.41) v1(13.46,57.15) v1(14.35,2.41) v1(16,57.15) v1(16.76,30.23) v1(16.89,2.41) v1(17.78,32.38) v1(18.54,57.66) v1(19.43,2.41) v1(20.95,57.66) v1(21.97,32) v1(21.97,2.41) v1(23.24,21.21) v1(23.62,57.15) v1(23.88,20.19) v1(24,30.48) v1(24.51,2.41) v1(25.27,30.23) v1(26.16,57.15) v1(27.05,19.05) v1(27.05,2.41) v1(28.32,25.53) v1(28.32,24.76) v1(28.7,57.15) v1(29.08,25.53) v1(29.08,24.76) v1(29.59,2.67) v1(30.99,28.96) v1(31.24,57.15) v1(31.24,31.11) v1(32.13,2.41) v1(32.51,18.8) v1(33.78,57.15) v1(34.67,2.41) v1(34.92,19.18) v1(35.31,23.37) v1(35.43,27.94) v1(36.32,57.15) v1(37.21,2.41) v1(38.86,57.15) v1(39.75,2.41) v1(41.4,57.15) v1(42.29,2.41) v1(43.94,57.15) v1(44.83,2.41) v1(46.48,57.15) v1(49.02,57.15) v1(50.16,46.99) v1(50.55,55.88) v1(50.55,38.1) v1(50.55,35.56) v1(50.55,34.54) v1(50.55,33.02) v1(50.55,31.37) v1(50.55,29.59) v1(50.55,27.94) v1(50.55,25.4) v1(50.55,18.54) v1(50.55,17.78) v1(50.55,10.16) v1(50.55,9.02) v1(50.55,7.62) v1(50.55,5.08) v1(50.55,2.54) v1(50.67,53.97) v1(50.93,47.24) v1(51.31,9.52) v1(51.44,53.59) v1(51.44,24.89) v1(51.56,38.73)
AGND_B: length 30.1
  TOP w0.279: v1(75.95,39.75) 75.95,39.88 75.96,39.89 U5.3
  TOP w0.305: 63.73,37.77 E11.1 ; E11.1 63.73,39.19 ; E11.1 64.48,38.48 ; U6.9 58.99,48.07 ; 63.88,39.51 R27.2 64.59,40.26
  TOP w0.33: C39.2 59.63,51.88 U6.15 ; 58.04,47.24 57.57,47.71 U6.9 ; 58.99,48.07 58.36,48.7 U6.10
  TOP w0.635: C33.1 v1(71.41,36.7) ; 65.45,37.59 C29.2 v1(66.17,38.48) ; v1(65.82,51.56) E2.2 v1(64.64,50.29) ; v1(72.01,40.39) C37.1 ; C34.1 v1(74.93,37.03) ; C39.2 v1(61.34,51.56)
  L3_PWR w0.635: GND2.1 64.4,51.55 ; GND2.1 64.4,53.35 ; GND2.1 62.6,53.35 ; GND2.1 62.6,51.55
  BOTTOM w0.635: GND2.1 62.6,51.55 ; GND2.1 62.6,53.35 ; GND2.1 64.4,53.35 ; GND2.1 64.4,51.55
  vias: v1(58.17,46.99) v1(58.67,56.01) v1(58.67,54.1) v1(58.93,46.74) v1(59.05,47.5) v1(60.45,56.01) v1(62.1,56.01) v1(64.26,56.01) v1(64.26,31.75) v1(65.41,38.86) v1(66.04,31.75) v1(66.8,56.01) v1(68.58,31.75) v1(69.34,56.01) v1(71.12,31.75) v1(71.88,56.01) v1(73.66,31.75) v1(74.42,56.01) v1(76.2,31.75) v1(76.96,56.01) v1(78.74,31.75) v1(79.5,56.01) v1(81.28,31.75) v1(82.04,56.01) v1(83.82,31.75) v1(84.58,56.01) v1(86.36,31.75) v1(87.12,56.01) v1(89.15,31.75) v1(89.66,56.01) v1(91.95,31.75) v1(92.2,56.01) v1(94.36,31.75) v1(94.74,56.01) v1(96.52,31.75) v1(96.77,56.01) v1(98.43,31.75) v1(99.06,56.01) v1(100.46,31.75) v1(101.47,55.63) v1(101.47,53.09) v1(101.47,50.55) v1(101.47,48.01) v1(101.47,45.47) v1(101.47,42.93) v1(101.47,40.39) v1(101.47,37.85) v1(101.47,35.31) v1(101.47,33.15)
AVDD1: length 7.7
  TOP w0.279: U1.26 73.55,15.98 73.41,16.13
  TOP w0.508: C11.2 73.28,16.26 73.41,16.13
  TOP w0.635: v1(69.15,9.08) E3.1 v1(68.07,10.03) ; C12.2 v1(70.74,15.37) ; C12.2 v1(69.6,16.29) ; C12.2 70.78,16.26 C11.2
AVDD2: length 7.6
  TOP w0.279: U5.26 73.55,44.81 73.41,44.96
  TOP w0.508: C35.2 73.28,45.08 73.41,44.96
  TOP w0.635: v1(68.07,38.86) E4.1 v1(69.15,37.91) ; C36.2 v1(70.74,44.2) ; C36.2 70.78,45.08 C35.2 ; C36.2 v1(69.72,45.12)
DVDD1: length 31.1
  TOP w0.279: 75.46,11.45 U1.2
  TOP w0.305: U3.16 58.86,23.68 58.99,23.81 ; C10.2 74.93,10.92 75.46,11.45
  TOP w0.508: 64.9,7.49 64.26,8.13 E8.1 ; R13.2 66.55,10.79 66.93,10.41 ; 73.03,8.89 74.55,10.41 C10.2 ; 58.99,23.81 59.18,24 59.94,24
  TOP w0.635: DVDD1.1 71.55,6.9 ; DVDD1.1 71.55,5.29 ; DVDD1.1 69.93,6.9 ; DVDD1.1 69.93,5.29 ; C13.1 67.18,7.49 67.5,7.18 E3.2 68.07,7.17 ; C13.1 65.28,7.49 ; C13.1 66.17,6.48 ; 73.97,8.89 C9.2 ; C9.2 73.03,8.89 ; C9.2 73.11,7.71 ; C17.1 v1(61.34,24) ; 61.34,24 59.94,24 ; 68.07,7.17 68.07,6.09 ; 68.07,7.17 69.01,7.17 ; R13.2 v1(67.44,11.43)
  L2_GND w0.635: DVDD1.1 71.64,5.2 ; DVDD1.1 71.64,6.99 ; DVDD1.1 69.84,5.2 ; DVDD1.1 69.84,6.99
  vias: v1(61.47,19.18) v1(62.23,18.29) v1(64.13,14.1) v1(64.64,16.38) v1(64.9,5.71) v1(67.06,18.92) v1(67.18,5.59) v1(67.44,13.97) v1(68.96,20.57) v1(69.72,8) v1(73.15,5.84) v1(75.18,4.95) v1(81.15,16.64) v1(81.79,17.27) v1(81.79,12.95) v1(84.2,7.37) v1(84.71,5.33) v1(85.85,8.25) v1(87.12,16) v1(87.25,22.1) v1(87.5,5.33) v1(87.76,12.06) v1(87.88,19.94) v1(95,4.83) v1(95.76,20.57) v1(95.88,17.78) v1(95.88,16.13) v1(96.01,13.84) v1(96.01,12.19) v1(96.01,8.25) v1(96.14,9.78) v1(96.14,6.22)
DVDD2: length 27.9
  TOP w0.279: U5.2 75.46,40.28 74.93,39.75 C34.2
  TOP w0.305: C39.1 59.63,52.51 U6.16
  TOP w0.508: C34.2 74.64,39.24 C33.2
  TOP w0.635: 66.17,35.31 C29.1 67.18,36.32 67.5,36 E4.2 ; E4.2 68.07,34.92 ; E4.2 69.41,36 ; 73.11,36.81 C33.2 73.97,37.72 ; DVDD2.1 71.55,34.12 ; DVDD2.1 69.93,35.73 ; DVDD2.1 71.55,35.73 ; DVDD2.1 69.93,34.12 ; C39.1 v1(61.34,52.83) ; R28.2 66.55,40.26
  TOP w0.762: E10.1 64.26,36.83 65.02,36.07
  L2_GND w0.635: DVDD2.1 71.64,34.03 ; DVDD2.1 71.64,35.82 ; DVDD2.1 69.84,35.82 ; DVDD2.1 69.84,34.03
  vias: v1(61.47,48.01) v1(62.23,47.12) v1(64.64,45.21) v1(64.64,42.93) v1(65.15,34.29) v1(67.06,47.75) v1(67.18,34.42) v1(67.44,42.8) v1(67.44,40.26) v1(68.96,49.4) v1(69.72,36.83) v1(74.17,34.16) v1(81.28,45.59) v1(81.79,46.1) v1(84.46,35.18) v1(85.34,34.54) v1(86.74,53.21) v1(86.74,37.21) v1(87.76,48.77) v1(90.04,52.96) v1(94.62,51.18) v1(94.62,34.16) v1(95,49.02) v1(95.38,41.02) v1(95.38,37.72) v1(95.63,44.96) v1(95.88,53.72) v1(96.14,38.61) v1(96.27,46.48) v1(96.39,49.02) v1(96.39,34.67) v1(96.52,42.67) v1(97.54,38.23)
GND_ISO: length 34.6
  TOP w0.279: v1(75.95,10.92) 75.95,11.05 75.96,11.06 U1.3
  TOP w0.305: 59.05,19.3 58.48,19.87 U3.10 ; 58.29,18.29 57.57,19.01 U3.9 58.99,19.24 v1(59.05,19.17) ; 63.73,10.49 63.73,10.45 ; C17.2 59.63,23.05 U3.15
  TOP w0.508: 63.73,10.45 E9.1 64.48,9.78
  TOP w0.635: C10.1 v1(74.93,8.25) ; C17.2 v1(61.34,22.73) ; 66.17,9.51 C13.2 65.45,8.76 ; v1(65.82,22.73) E1.2 v1(64.64,21.46) ; v1(72.01,11.56) C14.1 ; 64.9,10.68 R12.2 64.18,11.43 ; C9.1 v1(71.41,7.87)
  L3_PWR w0.635: GND1.1 62.6,24.52 ; GND1.1 64.4,22.73 ; GND1.1 64.4,24.52 ; GND1.1 62.6,22.73
  BOTTOM w0.635: GND1.1 64.4,22.73 ; GND1.1 64.4,24.52 ; GND1.1 62.6,22.73 ; GND1.1 62.6,24.52 ; 64.4,24.52 63.5,23.62 ; 63.5,23.62 64.4,22.72 ; 63.5,23.62 62.6,22.72 ; 63.5,23.62 62.6,24.52
  vias: v1(58.55,27.43) v1(58.55,24.89) v1(58.55,18.29) v1(59.31,18.54) v1(60.71,27.43) v1(62.61,27.43) v1(63.88,11.3) v1(65.02,2.41) v1(65.15,27.43) v1(65.15,9.27) v1(65.53,9.91) v1(67.56,2.41) v1(67.69,27.43) v1(70.1,2.41) v1(70.23,27.43) v1(72.64,2.41) v1(72.77,27.43) v1(75.18,2.41) v1(75.31,27.43) v1(77.72,2.41) v1(77.85,27.43) v1(80.26,2.41) v1(80.39,27.43) v1(82.8,2.41) v1(82.93,27.43) v1(85.34,2.41) v1(85.47,27.43) v1(88.01,27.43) v1(88.39,2.41) v1(90.55,27.43) v1(91.31,2.41) v1(93.09,27.43) v1(93.34,2.41) v1(95.12,27.43) v1(95.5,2.41) v1(97.28,27.43) v1(98.81,2.41) v1(99.69,27.18) v1(100.58,2.41) v1(101.6,26.67) v1(101.6,24.13) v1(101.6,21.46) v1(101.6,18.92) v1(101.6,16.38) v1(101.6,13.84) v1(101.6,11.3) v1(101.6,8.76) v1(101.6,6.22) v1(101.6,3.68)
VCC_PMOD: length 21.2
  L2_GND w0.635: 37.54,39.06 P5.12 39.42,39.06 ; 40.08,9.98 P4.6 41.96,9.98 ; 40.08,39.06 P5.6 41.96,39.06 ; 39.42,9.98 P4.12 37.54,9.98
  L2_GND w1.016: P4.12 P4.6
  L3_PWR w0.305: 41.96,9.98 41.85,10.1 ; 37.54,9.98 37.66,10.1
  L3_PWR w0.635: 38.92,5.15 PWR_SEL.1 38.92,7.04 ; 37.66,10.1 P4.12 39.42,9.98 ; 40.08,9.98 P4.6 41.85,10.1
CS_A_SDP: length 78.2
  TOP w0.254: v1(34.67,47.37) 34.67,48.39 34.28,48.78 U9.1
  TOP w0.305: v1(38.73,25.91) 38.73,28.7 33,34.44 SDP.85 ; U3.3 50.86,22.41 50.29,21.84 42.8,21.84 P4.1
  L3_PWR w0.254: v1(38.73,25.91) 38.73,34.54 34.67,38.61 v1(34.67,47.37)
  BOTTOM w0.305: v1(38.73,25.91) P4.1
CS_B_SDP: length 62.4
  TOP w0.254: U9.7 29.46,49.28 v1(32.26,46.48)
  TOP w0.305: SDP.37 v1(6.35,35.04) ; U6.3 50.86,51.24 50.29,50.67 45.85,50.67 43.81,52.7 P5.1
  BOTTOM w0.305: P5.1 39.75,51.43 37.21,51.43 v1(32.26,46.48) 20.81,35.04 v1(6.35,35.04)
CS_ISO1: length 20.8
  TOP w0.279: U1.32 74.25,12.98 72.92,12.98 v1(72.64,12.7)
  TOP w0.305: v1(69.72,15.36) 69.47,15.36 62.9,21.93 59.39,21.93 58.91,22.41 U3.14
  BOTTOM w0.279: v1(72.64,12.7) 72.39,12.7 v1(69.72,15.36)
CS_ISO2: length 20.8
  TOP w0.279: U5.32 72.93,41.81 v1(72.64,41.53) ; v1(69.09,44.2) 68.71,44.2 62.36,50.55 59.56,50.55 58.86,51.24 U6.14
  BOTTOM w0.305: v1(72.64,41.53) 72.14,41.53 69.47,44.2 v1(69.09,44.2)
IEXC_A: length 14.6
  TOP w0.279: R6.1 v1(86.36,11.18) ; v1(76.96,10.79) 76.96,10.92 76.46,11.42 U1.4
  TOP w0.305: R6.1 85.98,12.38 85.92,12.32 R8.1
  BOTTOM w0.305: v1(86.36,11.18) 77.34,11.18 v1(76.96,10.79)
IEXC_B: length 14.7
  TOP w0.279: v1(76.96,39.5) 76.96,39.67 76.46,40.17 U5.4
  TOP w0.305: R23.1 85.92,41.15 85.98,41.21 R21.1 v1(86.36,40.13)
  BOTTOM w0.305: v1(76.96,39.5) 85.72,39.5 v1(86.36,40.13)
SCL_0: length 22
  TOP w0.305: SDP.79 10.73,38.04 20.48,47.79 20.48,51.31 21.3,52.13 U8.6
SCLK_ISO1: length 19.7
  TOP w0.279: U1.30 74.25,13.98 69.33,13.98 62.36,20.95 58.93,20.95 58.74,21.14 U3.12
SCLK_ISO2: length 19.7
  TOP w0.279: U5.30 69.1,42.81 69.09,42.8 68.58,42.8 61.85,49.53 59.05,49.53 58.61,49.97 U6.12
SCLK_SDP: length 107.8
  TOP w0.305: U3.5 51.12,21.14 49.79,19.81 40.39,19.81 39.75,19.18 39.75,17.27 41.02,16 ; SDP.82 32.81,36.24 35.56,38.99 35.56,42.93 36.45,43.81 39.75,43.81 P5.4 39.75,46.35 39.75,48.26 40.39,48.89 50.04,48.89 51.12,49.97 U6.5
  BOTTOM w0.305: 41.02,16 42.42,17.4 42.42,19.18 41.78,19.81 40.51,19.81 39.75,20.57 39.75,21.72 40.39,22.35 42.8,22.35 43.18,22.73 43.18,44.07 42.16,45.08 P5.4
SDA_0: length 21.9
  TOP w0.305: SDP.80 10.89,37.44 21.08,47.62 21.08,51.05 21.5,51.48 U8.5
SDI_ISO1: length 19.7
  TOP w0.279: U1.29 74.25,14.48 69.54,14.48 62.58,21.44 59.18,21.44 58.84,21.78 U3.13
SDI_ISO2: length 19.7
  TOP w0.279: U5.29 68.83,43.31 62.1,50.04 59.31,50.04 58.74,50.61 U6.13
SDI_SDP: length 97
  TOP w0.305: SDP.84 33.42,35.04 39.75,28.7 39.75,22.35 41.15,20.95 50.17,20.95 50.99,21.78 U3.4 ; P5.2 50.55,50.16 50.99,50.61 U6.4
  BOTTOM w0.305: P5.2 43.94,47.24 43.94,22.35 42.67,21.08 41.02,21.08
SDO_A_SDP: length 43.5
  TOP w0.254: v1(35.43,46.86) 35.43,48.33 34.49,49.28 U9.2
  TOP w0.305: U3.6 51.3,20.51 49.72,18.92 v1(48.9,18.92)
  L3_PWR w0.254: v1(48.9,18.92) 39.24,28.57 39.24,34.81 35.43,38.62 v1(35.43,46.86)
SDO_B_SDP: length 30.2
  TOP w0.254: v1(30.73,51.31) 29.71,50.28 U9.5
  TOP w0.305: v1(46.35,48.01) 49.91,48.01 51.24,49.34 U6.6
  BOTTOM w0.305: v1(46.35,48.01) 46.35,51.43 43.9,53.89 33.31,53.89 v1(30.73,51.31)
SDO_SDP: length 81.2
  TOP w0.254: U9.3 U9.6
  TOP w0.279: U9.3 35.31,49.78 v1(36.32,48.77)
  TOP w0.305: v1(36.32,42.42) 36.32,38.73 33.23,35.64 SDP.83
  L2_GND w0.254: v1(36.32,48.77) 37.99,48.77 38,48.78 38.96,48.78 38.97,48.77 39.88,48.77 P5.3
  BOTTOM w0.305: 41.02,18.54 39.75,19.81 37.85,19.81 36.32,21.34 v1(36.32,42.42) 36.32,44.96 37.72,46.35 39.75,46.35 P5.3
UNNAMED_2_AD71244_I1_AIN1: length 18.6
  TOP w0.279: U1.5 76.96,11.79 77.62,11.12 77.62,10.35 76.96,9.69 C1.1
  TOP w0.305: v1(74.8,6.73) R3.2 75.69,9.07 76.28,9.65 C1.1 ; C3.1 v1(83.31,9.79)
  BOTTOM w0.305: v1(74.8,6.73) 78.86,6.73 81.93,9.79 v1(83.31,9.79)
UNNAMED_2_AD71244_I1_AIN2: length 3.4
  TOP w0.279: AIN2A.1 78.46,10.31 U1.8
UNNAMED_2_AD71244_I1_AIN3: length 23.7
  TOP w0.279: U1.9 80.11,12.98
  TOP w0.305: 80.11,12.98 80.41,12.98 82.04,11.35 C3.2 C2.2 v1(82.04,7.75) ; R4.2 v1(84.33,18.8)
  BOTTOM w0.305: v1(82.04,7.75) 82.8,8.51 84.96,8.51 87.08,10.63 87.08,14.77 84.33,17.53 v1(84.33,18.8)
UNNAMED_2_AD71244_I1_AIN4: length 3.8
  TOP w0.279: U1.16 79.73,16.48
  TOP w0.305: 79.73,16.48 R43.2
UNNAMED_2_AD71244_I1_AIN5: length 16.5
  TOP w0.279: 78.74,18.03 78.46,17.75 U1.17
  TOP w0.305: 78.74,18.03 79.25,18.03 C7.2 80.65,19.05 C62.1 v1(81.28,20.45) ; R39.2 v1(71.88,20.83)
  BOTTOM w0.305: v1(71.88,20.83) 80.77,20.83 81.15,20.45 v1(81.28,20.45)
UNNAMED_2_AD71244_I1_AIN6: length 6.8
  TOP w0.279: U1.20 76.96,17.78 77.34,18.16 77.85,18.16 78.61,18.92 C8.1
  TOP w0.305: R11.2 C7.1 80.01,20.32 78.99,19.3 C8.1
UNNAMED_2_AD71244_I1_DOUT: length 19
  TOP w0.279: v1(72.52,15.24) 72.78,14.98 74.25,14.98 U1.28
  TOP w0.305: v1(59.31,20.19) 58.99,20.19 58.67,20.51 U3.11
  BOTTOM w0.305: v1(72.52,15.24) 70.23,17.53 66.93,17.53 64.26,20.19 v1(59.31,20.19)
UNNAMED_2_AD71244_I1_REFIN1: length 5.5
  TOP w0.279: U1.13 80.51,14.98 C6.2
  TOP w0.305: C6.2 82.51,15.37 C5.2 82.93,15.79 R9.2
UNNAMED_2_AD71244_I1_REFIN1_1: length 5.5
  TOP w0.279: C6.1 80.51,14.48 U1.12
  TOP w0.305: C6.1 82.51,14.1 C4.1 82.93,13.68 R8.2
UNNAMED_2_AD71244_I1_REGCAPA: length 2.4
  TOP w0.279: 74.8,18.03 74.96,17.88 U1.24
  TOP w0.305: C15.2 74.04,18.8 74.8,18.03
UNNAMED_2_AD71244_I1_REGCAPD: length 2.7
  TOP w0.279: U1.1 74.96,11.71 74.68,11.43 74.04,11.43 C14.2
UNNAMED_2_ADUM5010_I94_GNDISO1: length 16.6
  TOP w0.305: R14.2 62.23,10.71 62.26,10.68 E9.2 61.53,9.78 61.4,9.65 C16.2 60.58,9.65 v1(59.82,10.41) 59.19,11.04 U2.11 ; U2.16 v1(59.82,14.29) 59.87,14.35 ; 59.87,14.35 59.87,15.95 59.58,16.24 U2.19 ; 59.87,14.35 59.87,13.95 59.57,13.64 U2.15
  BOTTOM w0.305: v1(59.82,14.29) v1(59.82,10.41)
UNNAMED_2_ADUM5010_I94_VSEL: length 8.3
  TOP w0.305: U2.13 60.22,12.34 R15.1 R14.1 R12.1 R13.1
UNNAMED_2_CAP_I52_N1: length 7.5
  TOP w0.305: E8.2 61.47,8.13 v1(61.34,8.25) 61.21,8.38 C16.1 ; U2.12 60.32,11.69 R15.2 60.83,11.18 v1(60.83,10.67)
  BOTTOM w0.305: v1(60.83,10.67) 60.83,9.49 61.34,8.98 v1(61.34,8.25)
UNNAMED_2_CAP_I124_N2: length 3.5
  TOP w0.305: R5.2 C56.2 83.31,20.07 R43.1
UNNAMED_2_CN4P_I6_N2: length 33.5
  TOP w0.305: v1(93.47,13.08) D4.C P1.2 ; R3.1 76.96,5.59 v1(77.72,4.83)
  BOTTOM w0.305: v1(93.47,13.08) 94.36,12.19 94.36,8 90.55,4.19 78.36,4.19 v1(77.72,4.83)
UNNAMED_2_CN4P_I6_N3: length 16.6
  TOP w0.305: P1.3 D5.C v1(93.47,16.76) ; R5.1 R4.1 86.61,18.73 v1(87.41,17.94)
  BOTTOM w0.305: v1(87.41,17.94) 92.3,17.94 v1(93.47,16.76)
UNNAMED_2_CN4P_I6_N4: length 8.1
  TOP w0.305: R1.1 D6.C P1.4
UNNAMED_2_RES_I79_N1: length 22.3
  TOP w0.305: v1(87.76,14.29) R6.2 86.36,16.68 85.89,17.14 R9.1 ; P1.1 D3.C v1(93.47,9.14)
  BOTTOM w0.305: v1(87.76,14.29) 90.11,14.29 93.47,10.92 v1(93.47,9.14)
UNNAMED_2_RES_I105_N1: length 18.5
  TOP w0.305: R10.1 79.25,22.73 79.76,23.24 R11.1 95.54,23.24 95.78,23 RT1.2
UNNAMED_3_AD71244_I22_AIN1: length 19.3
  TOP w0.279: U5.5 76.96,40.52 77.62,39.85 77.62,39.22 76.96,38.56 C21.1 76.07,38.23 75.69,37.85 R20.2 v1(74.68,35.31)
  TOP w0.305: C23.1 v1(83.31,38.62)
  BOTTOM w0.305: v1(83.31,38.62) 82.57,38.62 79.25,35.31 v1(74.68,35.31)
UNNAMED_3_AD71244_I22_AIN2: length 3.4
  TOP w0.279: U5.8 78.46,39.14 AIN2B.1
UNNAMED_3_AD71244_I22_AIN3: length 23.5
  TOP w0.279: 80.01,41.81 U5.9
  TOP w0.305: 80.01,41.81 81,41.81 82.04,40.77 C23.2 C22.2 v1(82.04,36.83) ; R18.2 v1(84.4,47.75)
  BOTTOM w0.305: v1(82.04,36.83) 83.06,37.85 85.09,37.85 87.12,39.88 87.12,43.81 84.4,46.53 v1(84.4,47.75)
UNNAMED_3_AD71244_I22_AIN4: length 3.8
  TOP w0.279: U5.16 79.73,45.31
  TOP w0.305: 79.73,45.31 R46.2
UNNAMED_3_AD71244_I22_AIN5: length 16.5
  TOP w0.279: 78.74,46.86 78.46,46.58 U5.17
  TOP w0.305: v1(81.28,49.28) C63.1 80.65,47.88 C27.2 79.25,46.86 78.74,46.86 ; R40.2 v1(71.88,49.66)
  BOTTOM w0.305: v1(81.28,49.28) 81.15,49.28 80.77,49.66 v1(71.88,49.66)
UNNAMED_3_AD71244_I22_AIN6: length 6.8
  TOP w0.279: U5.20 76.96,46.61 77.34,46.99 77.85,46.99 78.61,47.75 C28.1
  TOP w0.305: C28.1 78.99,48.13 80.01,49.15 C27.1 R26.2
UNNAMED_3_AD71244_I22_DOUT: length 19
  TOP w0.279: U5.28 73.84,43.81 73.84,43.81 73.53,43.81 v1(73.15,44.2)
  TOP w0.305: U6.11 58.48,49.34 59.05,48.77 v1(59.94,48.77)
  BOTTOM w0.305: v1(59.94,48.77) 64.64,48.77 66.93,46.48 70.87,46.48 v1(73.15,44.2)
